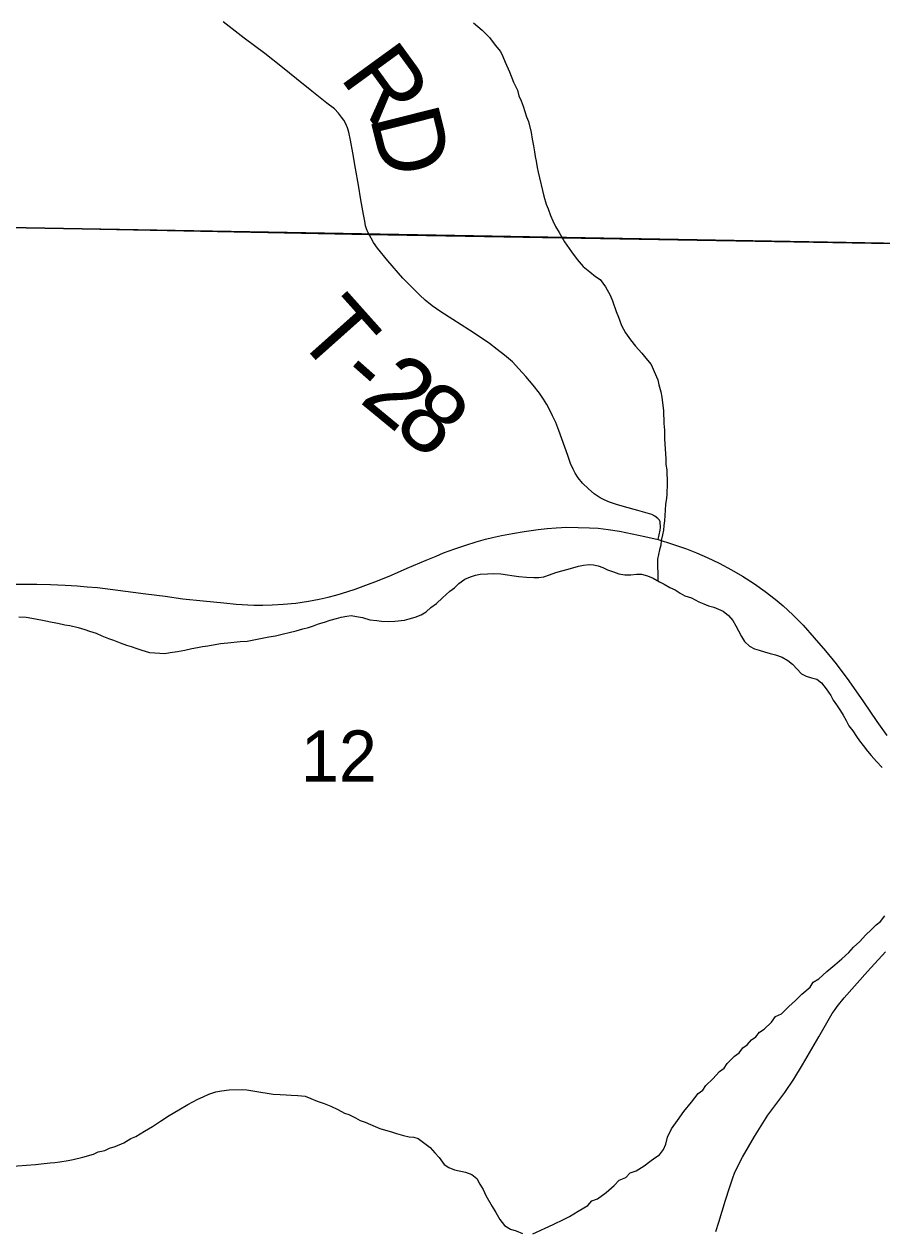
# Model space of a CAD drawing. Extents: x -7.9 to 76.1, y 0 to 22.
# Drawn here: x 3.631 to 4.333, y 17.437 to 18.425 of the extents above; entities that cross this region are included whole.
import ezdxf

# ---------------------------------------------------------------- set-up
doc = ezdxf.new("R2010")
doc.units = 0
for name, color, linetype in [('DV_X_Township_Line', 7, 'Continuous'), ('GM_X_Minor_River', 7, 'Continuous'), ('GM_X_Section', 7, 'Continuous'), ('GM_X_Section_Text', 7, 'Continuous'), ('GM_X_State_Route', 7, 'Continuous'), ('GM_X_Township_Road', 7, 'Continuous'), ('GM_X_Township_Road_Text', 7, 'Continuous')]:
    doc.layers.add(name, color=color, linetype=linetype)

msp = doc.modelspace()

# ---------------------------------------------------------------- linework, layer by layer
at = {"layer": 'DV_X_Township_Line'}
msp.add_lwpolyline([(5.3187, 14.1), (5.3187, 14.1), (5.33084, 14.5457), (5.34685, 15.15275), (5.34916, 15.24884), (5.34964, 15.26901), (5.3835, 16.83685), (5.40441, 17.61727), (5.42374, 18.23558), (4.96311, 18.23087), (4.78779, 18.23555), (4.71198, 18.23758), (4.64103, 18.23977), (3.91307, 18.25221), (2.81357, 18.27407), (2.77472, 18.27395), (2.7625, 18.27421), (2.75822, 18.27426), (2.1, 18.28619)], dxfattribs=at)
at = {"layer": 'GM_X_Minor_River'}
for points in [[(3.99915, 18.42575), (4.00607, 18.4198), (4.01222, 18.41384), (4.01688, 18.40748), (4.02113, 18.40224), (4.02309, 18.3981), (4.02506, 18.39359), (4.02861, 18.38569), (4.03179, 18.37702), (4.03493, 18.37063), (4.03614, 18.3661), (4.0381, 18.36196), (4.0397, 18.35743), (4.0425, 18.34876), (4.04408, 18.34499), (4.04612, 18.33593), (4.04698, 18.33063), (4.04821, 18.32496), (4.04905, 18.32005), (4.0495, 18.31626), (4.05032, 18.31248), (4.05117, 18.30719), (4.05199, 18.30341), (4.0565, 18.28376), (4.0585, 18.27735), (4.06008, 18.27359), (4.06207, 18.26793), (4.06404, 18.2638), (4.06601, 18.2589), (4.06912, 18.25402), (4.07342, 18.24651), (4.07924, 18.23827), (4.08389, 18.2319), (4.08891, 18.2263), (4.09428, 18.22184), (4.09889, 18.21813), (4.10272, 18.21555), (4.10698, 18.20955), (4.11089, 18.20279), (4.11286, 18.19827), (4.11566, 18.1896), (4.11764, 18.1847), (4.12003, 18.17791), (4.12354, 18.17191), (4.12742, 18.16629), (4.13167, 18.16105), (4.13669, 18.15545), (4.14017, 18.15134), (4.14442, 18.1461), (4.14679, 18.14045), (4.14994, 18.13368), (4.15077, 18.12952), (4.15238, 18.12386), (4.15322, 18.11932), (4.15409, 18.11251), (4.15454, 18.10834), (4.15473, 18.09772), (4.1552, 18.09242), (4.15533, 18.08521), (4.15637, 18.06892), (4.15645, 18.06437), (4.15729, 18.05983), (4.15748, 18.04883), (4.15725, 18.0401), (4.15694, 18.0363), (4.15627, 18.03173), (4.15597, 18.02679), (4.15567, 18.02261), (4.15537, 18.01806), (4.15468, 18.01425)], [(4.15468, 18.01425), (4.15437, 18.01045), (4.15368, 18.00664), (4.15262, 18.00207), (4.15231, 17.99827), (4.15124, 17.99446), (4.15055, 17.99065), (4.14948, 17.98684), (4.14997, 17.96902)], [(3.96887, 17.95062), (3.97371, 17.95526), (3.97967, 17.96068), (3.98341, 17.96341), (3.98713, 17.96689), (3.99199, 17.97039), (3.99649, 17.97236), (4.00063, 17.97358), (4.0044, 17.9744), (4.01045, 17.97489), (4.01574, 17.97498), (4.02142, 17.9747), (4.02673, 17.97404), (4.03053, 17.97335), (4.03622, 17.97269), (4.04228, 17.97204), (4.04834, 17.97176), (4.0525, 17.97184), (4.05666, 17.97229), (4.06117, 17.97389), (4.06643, 17.97588), (4.07133, 17.97711), (4.0766, 17.97872), (4.08488, 17.98114), (4.08903, 17.98197), (4.09356, 17.98243), (4.09735, 17.98212), (4.10115, 17.98143), (4.10496, 17.97998), (4.10877, 17.97815), (4.11372, 17.97634), (4.11791, 17.9749), (4.12285, 17.97384), (4.12777, 17.97393), (4.1323, 17.97439), (4.13646, 17.97447), (4.1414, 17.97304), (4.14598, 17.97122), (4.15133, 17.96828), (4.15514, 17.96645), (4.15973, 17.96349), (4.16393, 17.96167), (4.16814, 17.95909), (4.17196, 17.95688), (4.17729, 17.95508), (4.1834, 17.95177), (4.18759, 17.95033), (4.19141, 17.9485), (4.19559, 17.94743), (4.1994, 17.94598), (4.20321, 17.94415), (4.20781, 17.94082), (4.21129, 17.93671), (4.21364, 17.93219), (4.21598, 17.92806), (4.21833, 17.92355), (4.22067, 17.91942), (4.2249, 17.9157), (4.2291, 17.91349), (4.2329, 17.91242), (4.23709, 17.91098), (4.24166, 17.90954), (4.24622, 17.90848), (4.25155, 17.90668), (4.25614, 17.90373), (4.25998, 17.90076), (4.2673, 17.89292), (4.27112, 17.89109), (4.27569, 17.88965), (4.27987, 17.88859), (4.2837, 17.88562), (4.28757, 17.88076), (4.29145, 17.87513), (4.29341, 17.87137), (4.29613, 17.86763), (4.29924, 17.86275), (4.30158, 17.85899), (4.30392, 17.85486), (4.30627, 17.85035), (4.30937, 17.84623), (4.31248, 17.84173), (4.31481, 17.83798), (4.31791, 17.83424), (4.32139, 17.82974), (4.32448, 17.826), (4.32873, 17.82114), (4.33336, 17.81629)], [(3.627, 17.93962), (3.63306, 17.93935), (3.64066, 17.93796), (3.64787, 17.93658), (3.65433, 17.93517), (3.65888, 17.93449), (3.66458, 17.93308), (3.66875, 17.93239), (3.67559, 17.931), (3.68092, 17.92919), (3.68473, 17.92774), (3.69043, 17.92633), (3.69501, 17.92413), (3.70034, 17.92195), (3.70453, 17.92051), (3.70987, 17.91833), (3.7152, 17.91652), (3.719, 17.91545), (3.72357, 17.91364), (3.72776, 17.91219), (3.73384, 17.9104), (3.73839, 17.91011), (3.74635, 17.90949), (3.75087, 17.91033), (3.75691, 17.91119), (3.76295, 17.91244), (3.7686, 17.91368), (3.77312, 17.91452), (3.77727, 17.91535), (3.7818, 17.91581), (3.79198, 17.91789), (3.79803, 17.91837), (3.80823, 17.91931), (3.8139, 17.9198), (3.81918, 17.92065), (3.82483, 17.92189), (3.83162, 17.92315), (3.83691, 17.924), (3.84369, 17.92564), (3.84821, 17.92686), (3.85386, 17.92809), (3.85951, 17.92971), (3.86403, 17.93093), (3.86817, 17.93214), (3.8723, 17.93373), (3.8772, 17.93534), (3.88171, 17.93694), (3.88698, 17.93817), (3.89075, 17.93937), (3.89527, 17.94021), (3.89905, 17.94066), (3.90322, 17.93997), (3.90816, 17.93892), (3.91424, 17.93713), (3.91993, 17.93648), (3.92372, 17.93616), (3.92978, 17.93589), (3.9347, 17.93598), (3.94263, 17.93688), (3.94639, 17.93808), (3.95129, 17.93931), (3.95617, 17.94129), (3.96029, 17.94364), (3.96402, 17.94712), (3.96887, 17.95062)], [(4.0476, 17.43471), (4.06412, 17.44222), (4.07312, 17.44655), (4.07762, 17.44891), (4.08474, 17.45321), (4.0926, 17.45791), (4.09594, 17.46176), (4.10045, 17.46336), (4.10755, 17.46842), (4.11426, 17.47423), (4.11834, 17.47848), (4.1236, 17.48085), (4.12732, 17.48471), (4.13221, 17.48631), (4.13857, 17.49023), (4.14343, 17.49373), (4.14754, 17.49683), (4.15128, 17.49918), (4.1546, 17.50379), (4.15642, 17.508), (4.15783, 17.51372), (4.16112, 17.52061), (4.16591, 17.52753), (4.17108, 17.53483), (4.17738, 17.54253), (4.18293, 17.54946), (4.18667, 17.55219), (4.18925, 17.55603), (4.19483, 17.56144), (4.20039, 17.56761), (4.20413, 17.57034), (4.20671, 17.57418), (4.21266, 17.57998), (4.2164, 17.5827), (4.21935, 17.58693), (4.22309, 17.58927), (4.22642, 17.5935), (4.23017, 17.59585), (4.23312, 17.5997), (4.23687, 17.60204), (4.24282, 17.60784), (4.24614, 17.61245), (4.25102, 17.61482), (4.25697, 17.62062), (4.26256, 17.62565), (4.26777, 17.63068), (4.27448, 17.63649), (4.27705, 17.64071), (4.28154, 17.64344), (4.28825, 17.64926), (4.29459, 17.65468), (4.30055, 17.65972), (4.30614, 17.66476), (4.30984, 17.66937), (4.31506, 17.67402), (4.31989, 17.67904), (4.32472, 17.68368), (4.32844, 17.68754), (4.33218, 17.69027), (4.3355, 17.69488)], [(3.61866, 17.48976), (3.64058, 17.49128), (3.64776, 17.49217), (3.65267, 17.49264), (3.65644, 17.49308), (3.6606, 17.49353), (3.66739, 17.49479), (3.67154, 17.49562), (3.67945, 17.49728), (3.68811, 17.49972), (3.69186, 17.50168), (3.69752, 17.50292), (3.70127, 17.50488), (3.70578, 17.5061), (3.71292, 17.50926), (3.71853, 17.51278), (3.72267, 17.51437), (3.72978, 17.51867), (3.73652, 17.52259), (3.74288, 17.52687), (3.74998, 17.53155), (3.75785, 17.53625), (3.76534, 17.54056), (3.77359, 17.54488), (3.77772, 17.54685), (3.7826, 17.54883), (3.78824, 17.55083), (3.79277, 17.55167), (3.79918, 17.55254), (3.80977, 17.55273), (3.81356, 17.55242), (3.81849, 17.55175), (3.82495, 17.55072), (3.83026, 17.54968), (3.83519, 17.54901), (3.84087, 17.54873), (3.8458, 17.54844), (3.84997, 17.54813), (3.85527, 17.54784), (3.86134, 17.54719), (3.86591, 17.54537), (3.87124, 17.54319), (3.87695, 17.54139), (3.88229, 17.53921), (3.88802, 17.53628), (3.89337, 17.53333), (3.89717, 17.53226), (3.90251, 17.5297), (3.90633, 17.52749), (3.91052, 17.52605), (3.91472, 17.52422), (3.91853, 17.52239), (3.92234, 17.52094), (3.92691, 17.51951), (3.93185, 17.51807), (3.93604, 17.51663), (3.94174, 17.51521), (3.9463, 17.51416), (3.95009, 17.51384), (3.95389, 17.51277), (3.95926, 17.50869), (3.96348, 17.50535), (3.96735, 17.50086), (3.97082, 17.49713), (3.97508, 17.49151), (3.97891, 17.48892), (3.98348, 17.4871), (3.9926, 17.48499), (3.99755, 17.48318), (4.00178, 17.47983), (4.00413, 17.47532), (4.00685, 17.47081), (4.00921, 17.46592), (4.01429, 17.4569), (4.0174, 17.45202), (4.02053, 17.44638), (4.0244, 17.44152), (4.02937, 17.43857), (4.03394, 17.43713)], [(4.03394, 17.43713), (4.03927, 17.43495)]]:
    msp.add_lwpolyline(points, dxfattribs=at)
at = {"layer": 'GM_X_Section'}
for points in [[(3.41682, 19.27112), (4.43356, 19.25029), (4.41066, 18.24415), (3.38904, 18.26227)], [(3.38904, 18.26227), (4.41066, 18.24415), (4.39092, 17.41163), (3.3681, 17.4339)]]:
    msp.add_lwpolyline(points, close=True, dxfattribs=at)
at = {"layer": 'GM_X_State_Route'}
msp.add_lwpolyline([(3.62431, 17.96627), (3.63262, 17.96643), (3.64174, 17.96635), (3.65292, 17.96611), (3.665, 17.96553), (3.67471, 17.96487), (3.68284, 17.96421), (3.69139, 17.96347), (3.70405, 17.96191), (3.73085, 17.95846), (3.7468, 17.95641), (3.76134, 17.95443), (3.77779, 17.95262), (3.79464, 17.95097), (3.80475, 17.95007), (3.81938, 17.94925), (3.82678, 17.94917), (3.83431, 17.94929), (3.84321, 17.94989), (3.85366, 17.95089), (3.86393, 17.95237), (3.87289, 17.9541), (3.88013, 17.95575), (3.88629, 17.95739), (3.89114, 17.9588), (3.90212, 17.96227), (3.91083, 17.96542), (3.92042, 17.96901), (3.93192, 17.97367), (3.94475, 17.97935), (3.96028, 17.986), (3.96841, 17.98936), (3.97458, 17.99192), (3.98366, 17.99527), (3.9928, 17.99834), (4.00129, 18.00104), (4.00877, 18.0031), (4.01461, 18.00457), (4.02201, 18.00621), (4.03089, 18.00786), (4.0405, 18.00951), (4.05185, 18.01115), (4.05933, 18.01197), (4.06681, 18.01247), (4.07535, 18.01288), (4.09385, 18.01255), (4.10109, 18.01206), (4.10931, 18.01107), (4.1186, 18.00959), (4.12879, 18.00753), (4.13914, 18.00523), (4.15024, 18.00277), (4.16184, 17.99898), (4.17326, 17.99512), (4.18156, 17.99208), (4.19036, 17.98821), (4.20014, 17.98345), (4.21025, 17.97818), (4.21905, 17.97301), (4.22883, 17.96668), (4.23762, 17.96043), (4.24593, 17.9541), (4.25234, 17.94851), (4.26031, 17.94128), (4.26869, 17.93264), (4.2779, 17.92229), (4.28694, 17.91177), (4.29566, 17.90117), (4.30602, 17.88735), (4.3181, 17.87009), (4.32912, 17.85398), (4.33717, 17.84239)], dxfattribs=at)
at = {"layer": 'GM_X_Township_Road'}
for points in [[(3.91299, 18.25394), (3.91154, 18.25722), (3.9108, 18.25953), (3.91006, 18.26331), (3.90899, 18.26898), (3.90697, 18.28075), (3.90489, 18.29282), (3.90252, 18.30652), (3.90028, 18.31945), (3.89847, 18.32956), (3.897, 18.33614), (3.89593, 18.33975), (3.8942, 18.34354), (3.89288, 18.34609), (3.89116, 18.34855), (3.88869, 18.35176), (3.88524, 18.35537), (3.87916, 18.36006), (3.86675, 18.36992), (3.85421, 18.38001), (3.84274, 18.38924), (3.82835, 18.40051), (3.81151, 18.41308), (3.7943, 18.42647)], [(4.15024, 18.00277), (4.15181, 18.01048), (4.15204, 18.0128), (4.15173, 18.01721), (4.15111, 18.01876), (4.14995, 18.02016), (4.14747, 18.02202), (4.14484, 18.02325), (4.1412, 18.02449), (4.13346, 18.02658), (4.12247, 18.0296), (4.11605, 18.03145), (4.11032, 18.03339), (4.10606, 18.03525), (4.10274, 18.03703), (4.0977, 18.04036), (4.09306, 18.0443), (4.08834, 18.04903), (4.08478, 18.05336), (4.08223, 18.05707), (4.08052, 18.06048), (4.07836, 18.0652), (4.07611, 18.07163), (4.06892, 18.09221), (4.06628, 18.09856), (4.06373, 18.1042), (4.06149, 18.10885), (4.05901, 18.11326), (4.05645, 18.1176), (4.05313, 18.12255), (4.04778, 18.12921), (4.04175, 18.1364), (4.03625, 18.14267), (4.03099, 18.14825), (4.02433, 18.15374), (4.01846, 18.15838), (4.01203, 18.16319), (4.00367, 18.16914), (3.99578, 18.17433), (3.98208, 18.18292), (3.97225, 18.18926), (3.96513, 18.19422), (3.95956, 18.19878), (3.95514, 18.20281), (3.94887, 18.209), (3.94114, 18.21682), (3.92891, 18.2309), (3.92047, 18.2412), (3.9173, 18.24607), (3.91335, 18.25312), (3.91299, 18.25394)], [(4.19742, 17.43668), (4.1997, 17.44408), (4.20517, 17.46221), (4.20843, 17.47227), (4.21123, 17.4804), (4.21271, 17.48418), (4.21534, 17.4901), (4.21903, 17.49749), (4.22883, 17.51444), (4.23991, 17.53185), (4.25374, 17.55033), (4.26119, 17.5611), (4.26835, 17.57286), (4.28172, 17.5958), (4.29259, 17.61485), (4.29491, 17.61835), (4.29652, 17.6206), (4.30225, 17.62778), (4.32136, 17.64944), (4.33627, 17.66554)]]:
    msp.add_lwpolyline(points, dxfattribs=at)

# ---------------------------------------------------------------- texts
at = {"layer": 'GM_X_Section_Text'}
msp.add_text('12', height=0.041856, rotation=0.00001, dxfattribs=at).set_placement((3.85774, 17.80478))
at = {"layer": 'GM_X_Township_Road_Text'}
for s, rotation, p in [('R', 306.00184, (3.88894, 18.38121)), ('D', 284.09015, (3.91395, 18.34863)), ('T', 311.74352, (3.85211, 18.16966)), ('2', 320.51733, (3.90473, 18.11594)), ('-', 318.56019, (3.88563, 18.13276)), ('8', 320.76329, (3.93195, 18.09352))]:
    msp.add_text(s, height=0.05682, rotation=rotation, dxfattribs=at).set_placement(p)

doc.saveas('drawing.dxf')
